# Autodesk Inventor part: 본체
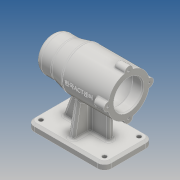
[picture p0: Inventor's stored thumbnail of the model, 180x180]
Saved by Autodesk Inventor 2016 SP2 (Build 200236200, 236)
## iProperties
Created: 2019-07
Part Number: 본체
Material: ABS 플라스틱
Document SubType Name: Modeling
Designer: EZ
Density: 1.06 g/cm^3
Appearance: 매끄러움 - 흰색
Mass: 252.637 g
Surface Area: 656.425 cm^2
Volume: 238.337 cm^3
Author: EZ
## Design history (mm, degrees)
sketch "스케치1"
  geometry: L1 (46, 35)-(-46, 35); L2 (-56, 25)-(-56, -25); L3 (-46, -35)-(46, -35); L4 (56, -25)-(56, 25); L5 (56, 35)-(-56, -35); L6 (-56, 35)-(56, -35); A1 r 10 centre (-46, 25) between (-46, 35) and (-56, 25); A2 r 10 centre (46, 25) between (56, 25) and (46, 35); A3 r 10 centre (46, -25) between (46, -35) and (56, -25); A4 r 10 centre (-46, -25) between (-56, -25) and (-46, -35); 1 further point
  constraints: 12 end point, 8 point on circle, 8 point on line, 8 tangent, 4 centre point, 3 equal radius, 2 midpoint, 2 parallel, 1 horizontal, 1 perpendicular
  dimensions: "d0" = 112 distance of L6.end L5.end; "d1" = 70 distance of L5.end L6.start; "d2" = 10 radius of A1
extrude "돌출1" new body sketch "스케치1" distance "d3" = 10; taper "d4" = 0 deg
sketch "스케치2"
  geometry: L1 (46, 35)-(-46, 35) reference; L2 (-56, 25)-(-56, -25) reference; L3 (-46, -35)-(46, -35) reference; L4 (56, -25)-(56, 25) reference; A1 r 10 centre (-46, 25) between (-46, 35) and (-56, 25) reference; A2 r 10 centre (-46, -25) between (-56, -25) and (-46, -35) reference; A3 r 10 centre (46, -25) between (46, -35) and (56, -25) reference; A4 r 10 centre (46, 25) between (56, 25) and (46, 35) reference; 5 further points
  constraints: 4 coincident
hole "구멍1" sketch "스케치2" at (-46, 25), (-46, -25), (46, -25), (46, 25) diameter "d5" = 6; stored, may be unused: countersink angle "d9" = 90 deg, drill point angle "d11" = 118 deg; dims "d6" = 6, "d7" = 4, "d8" = 2, "d10" = 8
sketch "스케치3"
  geometry: 1 further point
sketch "스케치4"
  geometry: L1 (0, 25)-(-80, 25); C1 r 30 at (-80, 25)
  constraints: 2 end point, 1 centre point, 1 coincident, 1 horizontal
  dimensions: "d12" = 80 distance of L1.start L1.end; "d13" = 60 diameter of C1
extrude "돌출2" join sketch "스케치4" distance "d14" = 67; taper "d15" = 0 deg
sketch "스케치6"
  geometry: C1 r 30 at (0, 0) reference; C2 r 25 at (0, 0); 1 further point
  constraints: 1 centre point, 1 coincident
  dimensions: "d16" = 50 diameter of C2
extrude "돌출3" join sketch "스케치6" distance "d17" = 20; taper "d18" = 0 deg
sketch "스케치7"
  geometry: C1 r 25 at (0, 0) reference; C2 r 25 at (0, 0); 1 further point
  constraints: 1 centre point, 1 coincident
  dimensions: "d19" = 50 diameter of C2
extrude "돌출4" join sketch "스케치7" distance "d20" = 25; taper "d21" = 0 deg
sketch "스케치8"
  geometry: L1 (56, 55)-(56, 105) reference; L2 (11, 105)-(11, 55) reference; L3 (11, 105)-(56, 105) reference; L4 (11, 50)-(11, 110) reference; L5 (-56, 50)-(-56, 110) reference; L6 (11, 105)-(31, 105); L7 (31, 105)-(11, 110); L8 (11, 110)-(11, 105); L9 (56, 80)-(-56, 80); 1 further point
  constraints: 8 end point, 2 midpoint, 1 collinear, 1 point on line
  dimensions: "d22" = 20 distance of L3.start L6.end
revolve "회전1" sketch "스케치8" stored, may be unused: angle "d23" = 90 deg
fillet "모깎기1" dims "d24" = 10
sketch "스케치10"
  geometry: C1 r 30 at (0, 0) reference; C2 r 21 at (0, 0); 1 further point
  constraints: 1 centre point, 1 coincident
  dimensions: "d41" = 42 diameter of C2
extrude "돌출5" cut sketch "스케치10" distance "d42" = 15; taper "d43" = 0 deg
sketch "스케치11"
  geometry: C1 r 21 at (0, 0) reference; C2 r 24 at (0, 0); 1 further point
  constraints: 1 centre point, 1 coincident
  dimensions: "d44" = 48 diameter of C2
extrude "돌출6" cut sketch "스케치11" distance "d45" = 54; taper "d46" = 0 deg
sketch "스케치12"
  geometry: C1 r 24 at (0, 0) reference; C2 r 21 at (0, 0); 1 further point
  constraints: 1 centre point, 1 coincident
  dimensions: "d47" = 42 diameter of C2
extrude "돌출7" cut sketch "스케치12" distance "d48" = 12; taper "d49" = 0 deg
sketch "스케치13"
  geometry: C1 r 25 at (0, 0) reference; C2 r 15 at (0, 0) reference; C3 r 17.5 at (0, 0); 1 further point
  constraints: 1 centre point, 1 coincident
  dimensions: "d50" = 35 diameter of C3
extrude "돌출8" cut sketch "스케치13" distance "d51" = 18; taper "d52" = 0 deg
sketch "스케치14"
  geometry: C1 r 17.5 at (0, 0) reference; C2 r 16 at (0, 0); 1 further point
  constraints: 1 centre point, 1 coincident
  dimensions: "d53" = 32 diameter of C2
extrude "돌출9" cut sketch "스케치14" distance "d54" = 4; taper "d55" = 0 deg
sketch "스케치15"
  geometry: C1 r 16 at (0, 0) reference; C2 r 10.5 at (0, 0); 1 further point
  constraints: 1 centre point, 1 coincident
  dimensions: "d56" = 21 diameter of C2
extrude "돌출10" cut sketch "스케치15" distance "d57" = 3; taper "d58" = 0 deg
sketch "스케치17"
  geometry: L1 (56, 25)-(56, -25) reference; L2 (56, 0)-(31, 0); L3 (0, 0)-(31, 0); L4 (31, 0)-(31, 4); L5 (31, 4)-(0, 4); L6 (0, 0)-(0, 4); L7 (0, 0)-(0, -4); L8 (0, -4)-(31, -4); L9 (31, -4)-(31, 0)
  constraints: 16 end point, 4 perpendicular, 2 horizontal, 1 midpoint, 1 point on line, 1 vertical
  dimensions: "d59" = 25 distance of L2.start L2.end; "d60" = 4 distance of L2.end L4.end; "d61" = 4 distance of L3.start L7.end
extrude "돌출11" join sketch "스케치17" stored distance "d62" = 3; taper "d63" = 0 deg
sketch "스케치18"
  geometry: L1 (0, 10)-(0, 50.268) reference; L2 (-46, 10)-(46, 10) reference; L3 (36, 10)-(20.57, 52.393); L4 (56, 0)-(56, 10) reference; L5 (11, 50)-(31, 55) reference; L6 (36, 10)-(0, 10); 1 further point
  constraints: 4 end point, 2 point on line, 1 collinear
  dimensions: "d64" = 110 deg angle of L2 L3; "d65" = 20 distance from line of L4 L3.start
feature "리브1" sketch "스케치18" dims "d66" = 1, "d67" = 8, "d68" = 0, "d69" = 0, "d70" = 1, "d71" = 1
sketch "스케치19"
  geometry: L1 (-4, 10)-(-4, 52.659) reference; L2 (22, 10)-(28, 10) reference; L3 (35, 10)-(25, 10) reference; L4 (28, 10)-(19.654, 57.334); L5 (35, 0)-(35, 10) reference; L6 (25, 10)-(-25, 10) reference; L7 (28, 10)-(4, 10); A1 r 30 centre (0, 80) between (4, 50.268) and (-4, 50.268) reference; 1 further point
  constraints: 4 end point, 2 point on line, 1 point on circle
  dimensions: "d74" = 100 deg angle of L3 L4; "d75" = 7 distance from line of L5 L4.start
feature "리브2" sketch "스케치19" dims "d76" = 1, "d77" = 8, "d78" = 0, "d79" = 0, "d80" = 1, "d81" = 1
sketch "스케치20"
  geometry: L1 (-4, 10)-(-4, 52.659) reference; L2 (25, 10)-(-25, 10) reference; L3 (-25, 10)-(-35, 10) reference; L4 (-28, 10)-(-19.654, 57.334); L5 (-35, 0)-(-35, 10) reference; L6 (-28, 10)-(-4, 10); A1 r 30 centre (0, 80) between (4, 50.268) and (-4, 50.268) reference; 1 further point
  constraints: 4 end point, 1 collinear, 1 point on circle, 1 point on line
  dimensions: "d82" = 100 deg angle of L3 L4; "d83" = 7 distance from line of L5 L4.start
extrude "돌출12" join sketch "스케치20" stored distance "d84" = 8; taper "d85" = 0 deg
sketch "스케치21"
  geometry: L1 (0, 0)-(-30, 0); L2 (0, 0)-(0, -30); L3 (0, 0)-(30, 0); L4 (0, 0)-(0, 30); C1 r 21 at (0, 0) reference; C2 r 6 at (-30, 0); C3 r 6 at (0, -30); C4 r 6 at (30, 0); C5 r 6 at (0, 30); A1 r 30 centre (0, 0) between (-30, 0) and (0, -30) reference; 1 further point
  constraints: 8 end point, 4 centre point, 4 coincident, 4 point on circle, 1 horizontal, 1 perpendicular, 1 point on line, 1 vertical
  dimensions: "d86" = 12 diameter of C2; "d87" = 12 diameter of C3; "d88" = 12 diameter of C4; "d89" = 12 diameter of C5
extrude "돌출13" join sketch "스케치21" distance "d90" = 16; taper "d91" = 0 deg
sketch "스케치22"
  geometry: A1 r 6 centre (-110, 25) between (-109.4, 30.97) and (-109.4, 19.03) reference; A2 r 6 centre (-80, 55) between (-74.03, 54.4) and (-85.97, 54.4) reference; A3 r 6 centre (-50, 25) between (-50.6, 19.03) and (-50.6, 30.97) reference; A4 r 6 centre (-80, -5) between (-85.97, -4.4) and (-74.03, -4.4) reference; 5 further points
  constraints: 4 coincident
hole "구멍2" sketch "스케치22" at (-80, 55), (-50, 25), (-80, -5), (-110, 25) diameter "d92" = 3.242; stored, may be unused: countersink angle "d96" = 90 deg, drill point angle "d98" = 118 deg; dims "d93" = 8, "d94" = 4, "d95" = 2, "d97" = 11
chamfer "모따기1" distance "d99" = 1; stored, may be unused: second distance "d100" = 2, angle "d101" = 45 deg
chamfer "모따기2" distance "d102" = 1; stored, may be unused: second distance "d103" = 2, angle "d104" = 45 deg
chamfer "모따기3" distance "d105" = 1; stored, may be unused: second distance "d106" = 2, angle "d107" = 45 deg
chamfer "모따기4" distance "d108" = 3; stored, may be unused: second distance "d109" = 2, angle "d110" = 45 deg
fillet "모깎기2" dims "d111" = 3
fillet "모깎기3" dims "d112" = 1
fillet "모깎기5" dims "d114" = 0.3
fillet "모깎기6" dims "d115" = 3
fillet "모깎기7" dims "d119" = 3
fillet "모깎기8" dims "d120" = 3
node "작업 평면2"
sketch "스케치24"
  geometry: L1 (0, -22)-(0, 22) reference; L2 (0, 0)-(-42, 0); 2 further points
  constraints: 2 end point, 1 coincident, 1 horizontal, 1 midpoint, 1 other
  dimensions: "d121" = 42 distance of L2.start L2.end
extrude "돌출15" join sketch "스케치24" distance "d122" = 0.5; taper "d123" = 0 deg
node "솔리드1"
node "투영된 루프1"
node "투영된 루프3"
node "투영된 루프4"
node "투영된 루프5"
node "투영된 루프6"
node "투영된 루프8"
node "투영된 루프9"
node "투영된 루프10"
node "투영된 루프11"
node "투영된 루프12"
node "투영된 루프13"
node "투영된 루프14"
